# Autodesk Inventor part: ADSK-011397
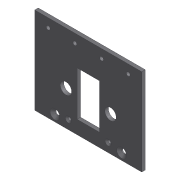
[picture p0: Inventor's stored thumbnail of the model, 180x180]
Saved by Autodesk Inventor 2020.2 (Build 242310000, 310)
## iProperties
Created: 2000-01
Part Number: ADSK-011397
Material: Acier doux
Description: PLT-CP,FH,XX,03,120,097,PLT,MNT,VERT
Document SubType Name: Modeling
Designer: sspink
Density: 7.86 g/cm^3
Appearance: Metal-Steel(Polish)
Mass: 5077.86 g
Surface Area: 1493.22 cm^2
Volume: 646.038 cm^3
Control State: 0
Checked Out: False
Master: False
Shininess: 0.0
Length Units: 11269
Angle Units: 11279
Time Units: 11290
Mass Units: 11283
Length Display Precision: 3
Angle Display Precision: 2
Compacted: True
Dimensions: 247,5x10x305 mm
Mass: 5,078 kg
DocNumber: ADSK-011397.ipt
Folder: 01 - Themengebiete\Simplification\01 - Packaging machine\
VDS_Category: 3D Komponenten
VLT_Material: Acier doux
Density: 0.0
Volumn: 0.0
Area: 0.0
PropertySet Name: Model Information
Author: sspink
Revision Number: -
Title: PLT-CP,FH,XX,03,120,097,PLT,MNT,VERT
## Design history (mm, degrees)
node "Solide1"
  node "Extrusion1" dims "d2" = 10, "d3" = 0
  node "Hole1" dims "d16" = 32.5, "d17" = 9.525, "d18" = 6.35, "d19" = 60 deg, "d20" = 19.05, "d21" = 118 deg, "d61" = 6
  node "Extrusion3" dims "d26" = 25.4, "d27" = 0
  node "Hole2" dims "d33" = 11, "d34" = 9.525, "d35" = 6.35, "d36" = 60 deg, "d37" = 19.05, "d38" = 118 deg, "d56" = 6
  node "Hole3" dims "d43" = 9, "d44" = 17.3, "d45" = 6.35, "d46" = 90 deg, "d47" = 19.05, "d48" = 118 deg, "d57" = 6
sketch "Sketch1"
  geometry: L1 (-152.5, -123.75)-(152.5, -123.75); L2 (152.5, -123.75)-(152.5, 123.75); L3 (152.5, 123.75)-(-152.5, 123.75); L4 (-152.5, 123.75)-(-152.5, -123.75); 3 further points
  constraints: 8 end point, 2 midpoint, 2 parallel, 1 horizontal, 1 horizontal alignment, 1 perpendicular, 1 vertical alignment
  dimensions: "d0" = 247.5 distance of L3.end L1.start; "d1" = 305 distance of L1.start L1.end
sketch "Sketch2"
  geometry: L1 (-152.5, 123.75)-(152.5, 123.75) reference; L2 (-95, -104.85)-(95, -104.85); L3 (152.5, -123.75)-(-152.5, -123.75) reference; C1 r 6.747 at (-95, -104.85); C2 r 6.747 at (95, -104.85); 2 further points
  constraints: 2 centre point, 2 end point, 2 midpoint, 1 equal radius, 1 horizontal, 1 horizontal alignment, 1 vertical alignment
  dimensions: "d4" = 190 distance of L2.end L2.start; "d7" = 13.49375 diameter of C1; "d39" = 228.6 distance from line of L2.start L1
workplane "Arbeitsebene1"
hole "Bohrung4" sketch "Sketch2" diameter "d49" = 13.5; stored, may be unused: countersink angle "d53" = 90 deg, drill point angle "d55" = 118 deg; dims "d50" = 6, "d51" = 28, "d52" = 8.6, "d54" = 8
sketch "Sketch3"
  geometry: L1 (-152.5, 123.75)-(152.5, 123.75) reference; L2 (63.5, -25.25)-(-63.5, -25.25); 2 further points
  constraints: 2 end point, 2 midpoint, 1 horizontal, 1 horizontal alignment, 1 vertical alignment
  dimensions: "d14" = 127 distance of L2.end L2.start; "d15" = 149 distance from line of L2.start L1
sketch "Sketch4"
  geometry: L1 (-152.5, -123.75)-(-152.5, 123.75) reference; L2 (152.5, -123.75)-(-152.5, -123.75) reference; L3 (152.5, 123.75)-(152.5, -123.75) reference; L4 (-152.5, 123.75)-(152.5, 123.75) reference; L5 (0, 123.75)-(0, -123.75); L6 (-152.5, 0)-(152.5, 0); L7 (-31.75, 41.25)-(31.75, 41.25); L8 (31.75, 41.25)-(31.75, -85.75); L9 (31.75, -85.75)-(-31.75, -85.75); L10 (-31.75, -85.75)-(-31.75, 41.25)
  constraints: 12 end point, 4 midpoint, 2 parallel, 1 horizontal, 1 perpendicular
  dimensions: "d22" = 63.5 distance of L7.start L7.end; "d23" = 31.75 distance between parallel lines of L10 L5 (= 0.5 x d22); "d24" = 82.5 distance between parallel lines of L7 L4; "d25" = 127 distance of L9.end L7.start
sketch "Sketch5"
  geometry: L1 (-152.5, 123.75)-(152.5, 123.75) reference; L2 (-114, 98.75)-(114, 98.75); 4 further points
  constraints: 3 horizontal alignment, 2 end point, 2 midpoint, 1 horizontal, 1 vertical alignment
  dimensions: "d28" = 25 distance from line of L2.end L1; "d58" = 228 distance of L2.start L2.end; "d59" = 76 distance of L2.end point (38, 98.75) (= 0.333333 x d58); "d60" = 76 distance of L2.start point (-38, 98.75) (= 0.333333 x d58)
sketch "Sketch6"
  geometry: L1 (-31.75, -85.75)-(-31.75, 41.25) reference; L2 (31.75, 41.25)-(31.75, -85.75) reference; L3 (152.5, -123.75)-(-152.5, -123.75) reference; 2 further points
  constraints: 1 horizontal alignment
  dimensions: "d40" = 25 distance from line of point (-56.75, -98.75) L3; "d41" = 25 distance from line of point (56.75, -98.75) L2; "d42" = 25 distance from line of L1 point (-56.75, -98.75) (= d41)
node "Corps solides"
node "Corps surfaciques"
